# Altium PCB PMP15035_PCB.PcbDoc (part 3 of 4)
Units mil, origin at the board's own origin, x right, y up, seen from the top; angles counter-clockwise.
Board outline 5645 x 4585 mil, 8 copper layers (Top Layer, Signal Layer 1, Signal Layer 2, Signal Layer 3, Signal Layer 4, Signal Layer 5, Signal Layer 6, Bottom Layer), stack 60.9 mil thick; 335 components, 164 nets, 981 pads, 1349 vias.
Unrouted connection lines stored in the file: 46.
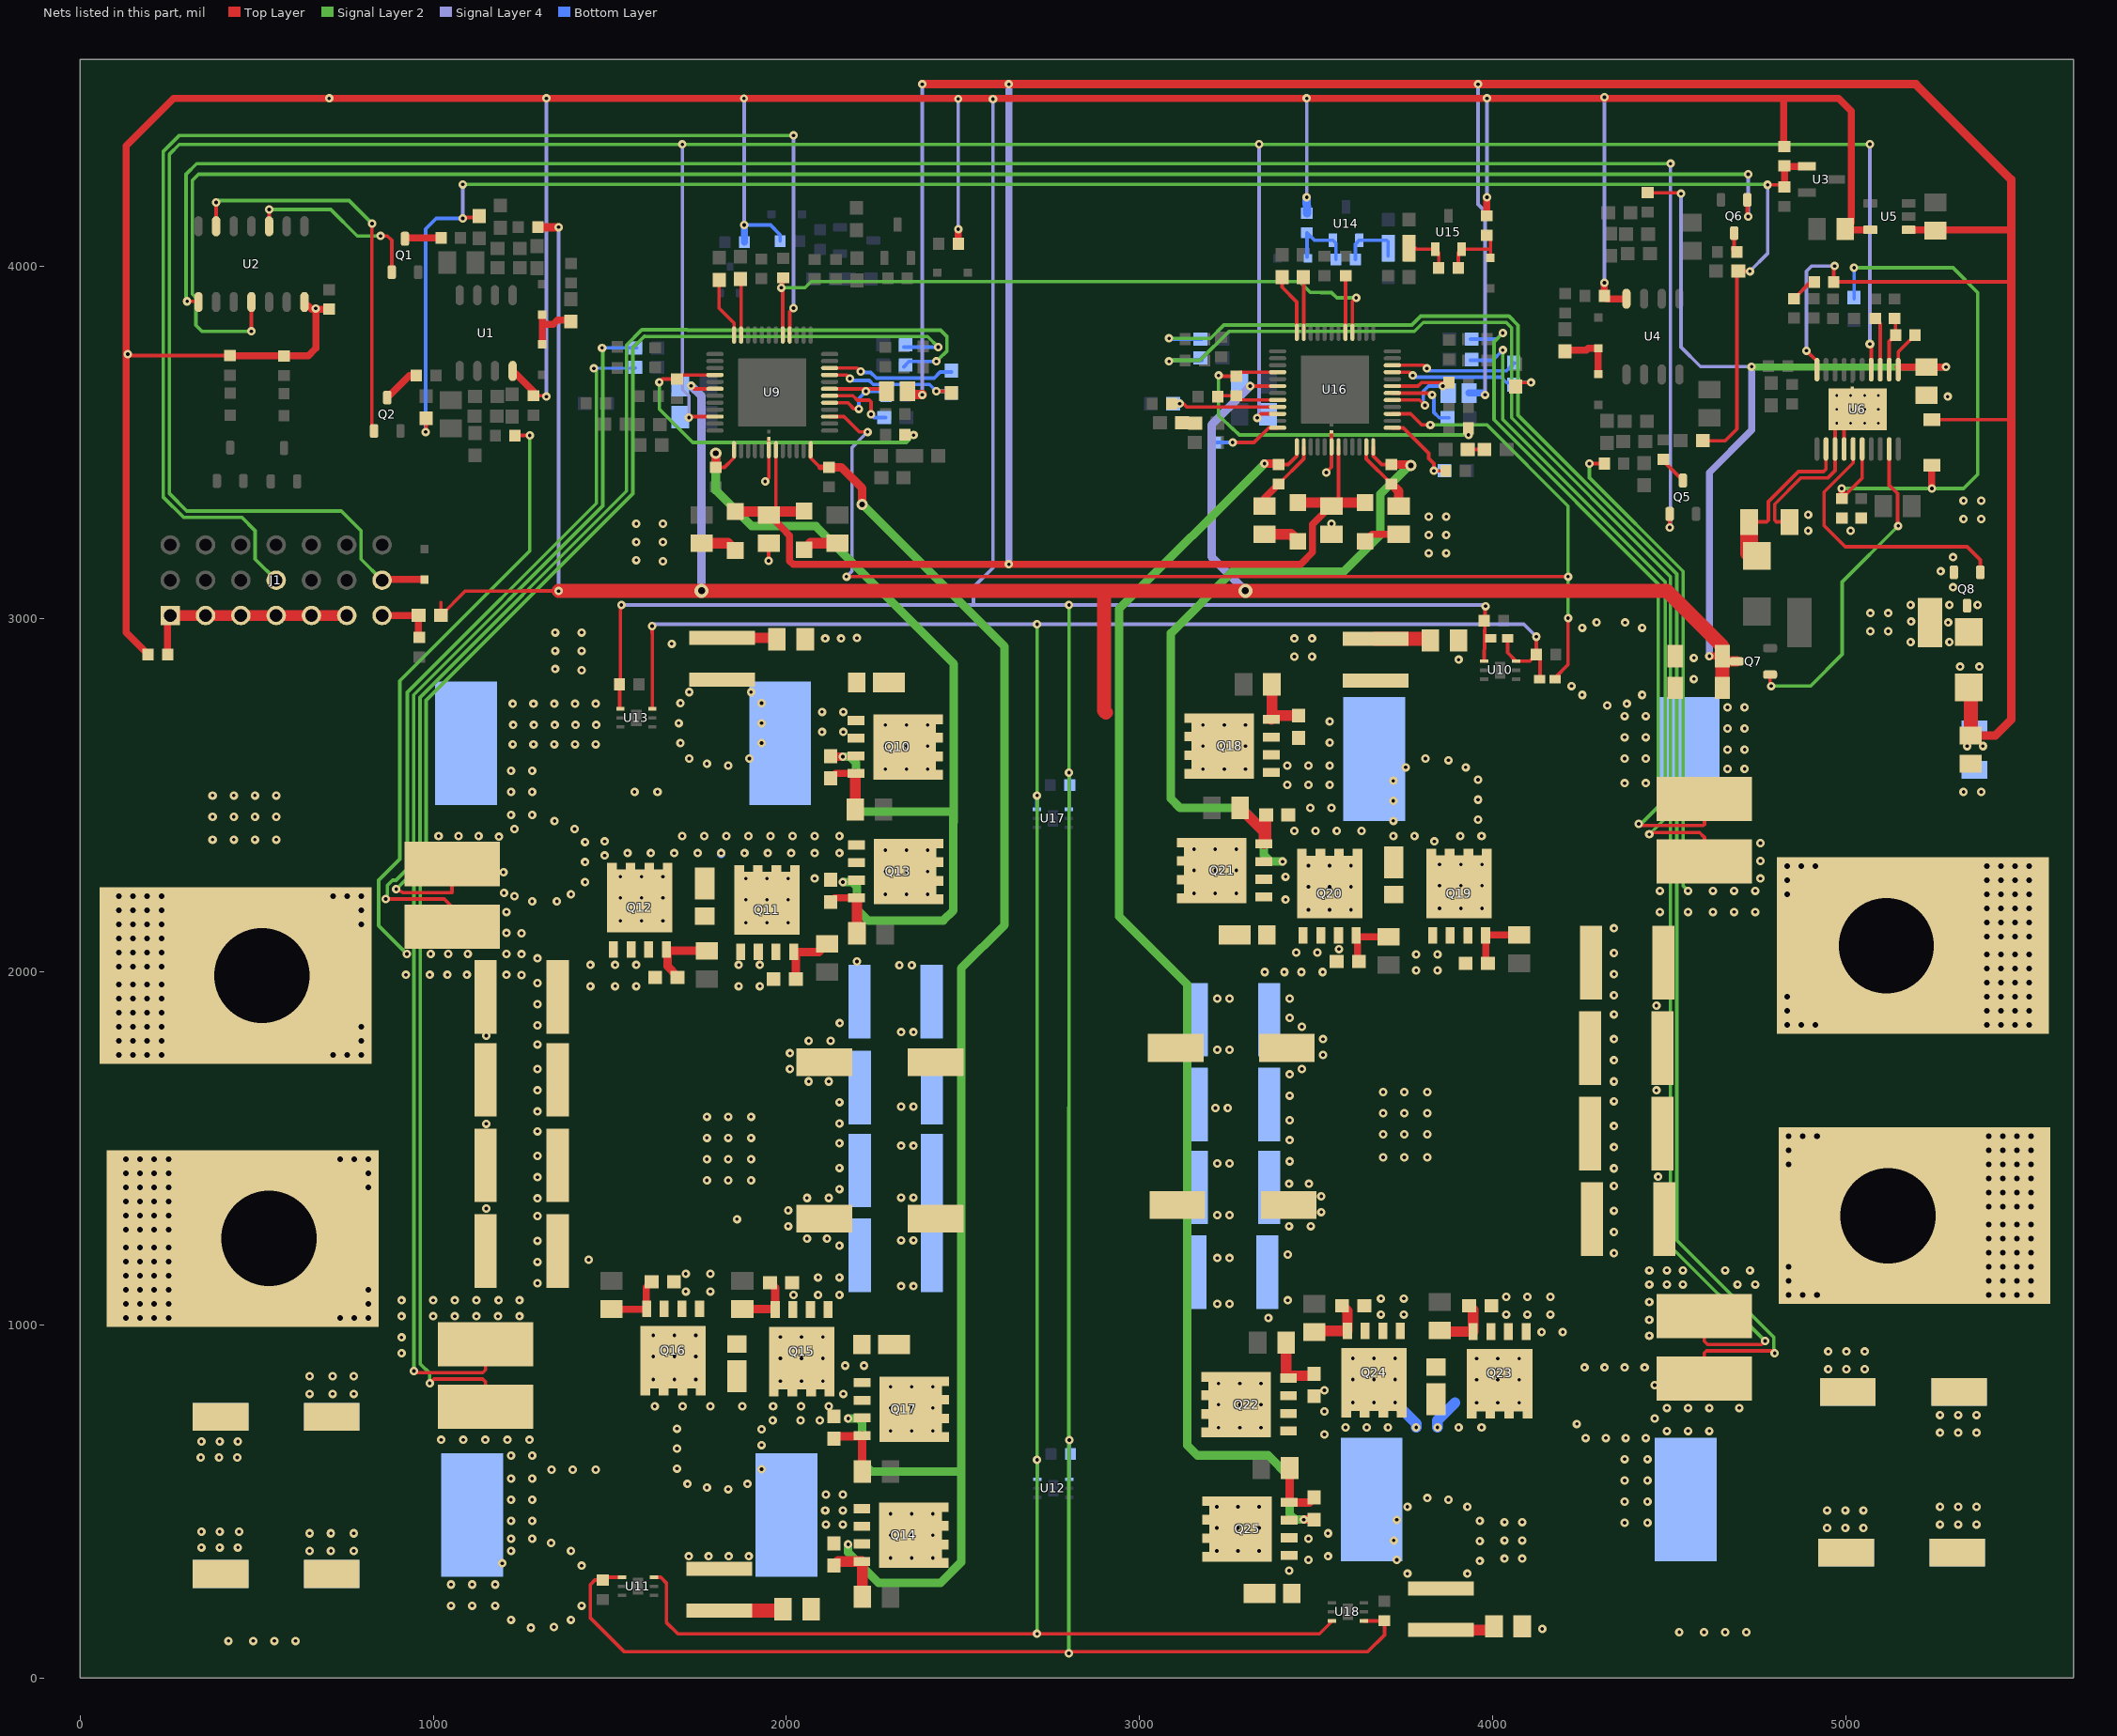
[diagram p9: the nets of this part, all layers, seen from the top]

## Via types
v1: diameter 24, hole 10, Top Layer to Bottom Layer, tented both sides, 873 vias
v2: diameter 32, hole 16, Top Layer to Bottom Layer, 237 vias
v3: diameter 24, hole 10, Top Layer to Bottom Layer, 145 vias
v4: diameter 19.68, hole 7.87, Top Layer to Bottom Layer, 62 vias
v5: diameter 32, hole 16, Top Layer to Bottom Layer, tented both sides, 14 vias
v6: diameter 23, hole 10, Top Layer to Bottom Layer, tented both sides, 5 vias
v7: diameter 19.68, hole 7.87, Top Layer to Bottom Layer, tented top, 4 vias
v8: diameter 19.68, hole 7.87, Top Layer to Bottom Layer, tented bottom, 2 vias
v9: diameter 40, hole 20, Top Layer to Bottom Layer, tented both sides, 2 vias
v10: diameter 24, hole 10, Top Layer to Bottom Layer, tented bottom, 2 vias
v11: diameter 22, hole 10, Top Layer to Bottom Layer, tented both sides, 1 vias
v12: diameter 24/24/24/24/24/24/24/24 (per signal layer), hole 10, Top Layer to Bottom Layer, tented both sides, 1 vias
v13: diameter 26, hole 10, Top Layer to Bottom Layer, tented both sides, 1 vias

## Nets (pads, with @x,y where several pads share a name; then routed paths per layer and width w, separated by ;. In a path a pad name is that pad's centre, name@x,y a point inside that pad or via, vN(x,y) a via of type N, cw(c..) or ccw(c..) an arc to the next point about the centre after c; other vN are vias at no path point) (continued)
NetC62_1: C62.1 R67.1 R72.2 U14.1 | length 183.2
  Bottom Layer w10: C62.1@3611.31,4018.7 3611.31,4061.66 U14.1@3622.4,4072.76 3699.99,4072.76 R72.2@3704.25,4068.5 R67.1@3704.25,4031.5 R67.1@3704.25,4027.56
NetC62_2: C62.2 D16.1 R66.2 U14.2 | length 209.1
  Bottom Layer w10: D16.1@3474.24,4025.26 R66.2@3474.24,4094.39 3495.88,4072.76 U14.2@3547.6,4072.76 3556.19,4064.17 C62.2@3556.19,4018.7
NetC63_1: C63.1 R69.1 R73.2 U15.1 | length 184.2
  Top Layer w10: R69.1@3763.75,4027.56 R69.1@3763.75,4031.5 R73.2@3763.75,4068.5 ; R73.2@3763.75,4072.44 R73.2@3763.75,4068.5 ; C63.1@3847.44,3995 3847.44,4037.91 U15.1@3837.6,4047.76 3784.5,4047.76 R73.2@3763.75,4068.5
NetC63_2: C63.2 D17.1 R68.2 U15.2 | length 192.7
  Top Layer w10: C63.2@3902.56,3995 3902.56,4037.91 U15.2@3912.4,4047.76 3991.5,4047.76 3993.75,4050 ; D17.1@3993.75,4023.31 3993.75,4050 ; R68.2@3993.75,4076.87 3993.75,4050
NetC65_1: C65.1 R70.1 | length 54.9
  Top Layer w10: C65.1@3925.76,3480 R70.1@3980.64,3480
NetC66_1: C66.1 R71.2 U16.8 | length 176
  Top Layer w10: C66.1@3221.31,3630 3223.75,3632.44 R71.2@3273.75,3632.44 3285.72,3620.47 U16.8@3391.35,3620.47
NetC73_2: C73.2 R77.1 U16.23 | length 205.5
  Top Layer w10: U16.23@3642.33,3487.6 3642.33,3453.86 C73.2@3713.75,3382.44
  Top Layer w26: C73.2@3713.75,3382.44 3733.75,3362.44 R77.1@3733.75,3320
NetC78_1: C78.1 R83.1 U16.14 | length 213.7
  Top Layer w10: C78.1@3393.75,3382.44 3465.17,3453.86 U16.14@3465.17,3487.6
  Top Layer w20: R83.1@3353.75,3320 3353.75,3342.44 C78.1@3393.75,3382.44
NetC80_1: C80.1 U16.12 | length 193.1
  Top Layer w10: v1(3263.75,3500) 3324.2,3500 3365.94,3541.73 U16.12@3391.35,3541.73
  Bottom Layer w10: C80.1@3215.56,3500 v1(3263.75,3500)
NetC85_2: C85.2 R86.2 | length 43.6
  Top Layer w10: R86.2@3118.16,3554.41 C85.2@3161.74,3554.41
NetC86_1: C86.1 R84.2 U16.9 | length 282
  Top Layer w10: v1(3113.75,3610) 3124.54,3610 3134.14,3600.39 3391.35,3600.39 U16.9@3391.35,3600.79
NetC87_1: C87.1 R85.2 U16.25 | length 251.9
  Top Layer w10: U16.25@3716.15,3541.73 3747.02,3541.73 3818.87,3469.87 3818.87,3455.13 3833.75,3440.25 v1(3833.75,3420) ; v1@3837.88,3420 C87.1@3867.49,3420
  Bottom Layer w10: v1(3833.75,3420) R85.2@3867.49,3420
NetC92_1: C92.1 R89.1 | length 151
  Top Layer w30: R89.1@1818.15,2946.48 C92.1@1969.15,2946.48
NetC93_1: C93.1 R101.1 | length 131.7
  Top Layer w40: R101.1@1835,191 C93.1@1966.67,191
NetC110_1: C110.1 R113.1 | length 151
  Top Layer w40: R113.1@3668.47,2943.41 C110.1@3819.47,2943.41
NetC111_1: C111.1 R125.1 | length 139.3
  Top Layer w30: R125.1@3853.75,136 C111.1@3993.06,136
NetD1_1: D1.1 D2.1 R7.1 | length 170.3
  Top Layer w20: D2.1@1308.39,3778.31 1308.39,3834.19 ; D1.1@1308.39,3861.69 1308.39,3834.19 ; R7.1@1390,3846.87 1351.76,3846.87 1339.07,3834.19 1308.39,3834.19
NetD5_1: D5.1 D6.1 R22.1 | length 169.2
  Top Layer w20: R22.1@4205.36,3761.89 4265.45,3761.89 4270.57,3767.01 D6.1@4299.06,3767.01 D5.1@4299.06,3693.62
NetD8_2: D8.2 L1.2 Q8.3
  other v1: 5183.75,2935 5293.75,2935 5290.25,2990 5184.93,2992.63 5293.75,3039.49 5373.75,3039.49 5183.75,3040
NetD9_2: D9.2 R34.2 U6.12 | length 455.9
  Top Layer w10: R34.2@4726.66,3275 4776.01,3275 4781.01,3280 4781.01,3332.54 4866.34,3417.87 4937.62,3417.87 4944.18,3424.43 U6.12@4944.18,3481.8
  Top Layer w50: D9.2@4726.66,3186.65 R34.2@4726.66,3275
NetD12_1: D12.1 R53.2 | length 102.6
  Top Layer w30: D12.1@2050.16,3195.83 2068.94,3214.61 R53.2@2145,3214.61
NetD13_1: D13.1 R58.2 | length 103.3
  Top Layer w30: R58.2@1760,3214.61 1834.88,3214.61 D13.1@1855,3194.49
NetD18_1: D18.1 R77.2 | length 103.3
  Top Layer w20: D18.1@3638.75,3219.88 3658.87,3240 R77.2@3733.75,3240
NetD19_1: D19.1 R83.2 | length 103.3
  Top Layer w30: R83.2@3353.75,3240 3428.63,3240 D19.1@3448.75,3219.88
NetJ1_1: J1.1 J1.4 J1.7 J1.10 J1.13 J1.16 R59.1 | length 613.1
  Top Layer w20: R59.1@247.56,2900 247.56,3002.56 J1.1@255,3010
  Top Layer w30: J1.1@255,3010 J1.4@355,3010 J1.7@455,3010 J1.10@555,3010 J1.13@655,3010 J1.16@755,3010
NetJ1_19: J1.19 R63.2 R64.2 | length 161.6
  Top Layer w20: J1.19@855,3010 947.44,3010 957.44,3000 R64.2@957.44,2945
NetL8_1: L8.1 R87.2 R103.2 | length 2119.5
  Top Layer w10: v1(895,2235) 915,2225 1052.76,2225 1053.15,2225.39 R87.2@1053.15,2306.06
  Signal Layer 2 w10: v1(895,2235) 944.25,2284.25 944.25,2784.81 1479.87,3320.43 1479.87,3766.23 v1(1477.99,3768.11) v1@1475.16,3770.94
  Bottom Layer w10: v1(1477.99,3768.11) R103.2@1572.01,3768.11 R103.2@1575.95,3768.11
  other v1: 1280,2200 1350,2200 1229.96,2215 1390,2220 1200,2224.21 1430,2254.96 1198.82,2282.57 1430,2311.64 1485,2330 1430,2368.32 1485,2370 1186.18,2383.32 1014.96,2385 1071.64,2385 1128.32,2385 1230,2405 1400.04,2405 1343.36,2427.43 1220,2445 1280,2445 1220,2510 1280,2510 1220,2570 1280,2570 1225,2645 1283.75,2645 1342.5,2645 1401.25,2645 1460,2645 1226.25,2700 1285,2700 1343.75,2700 1402.5,2700 1461.25,2700 1225,2760 1283.75,2760 1342.5,2760 1401.25,2760 1460,2760
NetL9_2: L9.2 R93.2 R99.2 | length 4420.2
  Top Layer w10: v1(990,835) 1002.13,847.13 1140,847.13 1148.15,838.98 R99.2@1148.15,768.9
  Signal Layer 2 w10: v1(990,835) 990,862.87 962.87,890 962.87,2252.32 980,2269.44 980,2770 1565,3355 1565,3768.6 1598.2,3801.8 1600,3800 2400,3800 v1(2430,3770)
  Bottom Layer w10: R93.2@2332.56,3770 v1(2430,3770)
  other v1: 1276.64,142.57 1341.9,144.28 1219.96,165 1390,165 1050,205 1110,205 1175,205 1420,205 1050,265 1110,265 1175,265 1420,318.36 1195,325 1219.96,360 1390,360 1333.32,382.43 1220,395 1280,395 1220,445 1280,445 1220,505 1280,505 1220,565 1280,565 1335,590 1395,590 1460,590 1220,630 1280,630 1022.5,675 1085,675 1147.5,675 1210,675 1272.5,675
NetL10_2: L10.2 R111.1 R116.2 | length 1980.5
  Top Layer w10: v1(4413.75,2420) 4418.75,2415 4596.19,2415 4599.97,2418.78 R111.1@4599.97,2490.59
  Signal Layer 2 w10: v1(4028.75,3810) 4003.87,3785.13 4003.87,3564.87 4468.75,3100 4468.75,2467.87 4420.87,2420 v1(4413.75,2420)
  Bottom Layer w10: R116.2@3936.86,3792.8 R116.2@3940.8,3792.8 4011.54,3792.8 v1(4028.75,3810)
  other v1: 4373.75,2535 4433.75,2535 4665,2575.59 4713.75,2575.59 4373.75,2605 4433.75,2605 4665,2630 4713.75,2630 4373.75,2665 4433.75,2665 4665,2690 4713.75,2690 4373.75,2725 4433.75,2725 4665,2750 4713.75,2750 4325,2755 4380,2760 4253.71,2785 4423.75,2785 4223.75,2810 4253.71,2975 4423.75,2975 4375,2990 4294.53,2990.86
NetL11_1: L11.1 R123.1 R126.2 | length 4605.9
  Top Layer w10: R123.1@4599.59,847.94 4599.59,920.85 4605.87,927.13 4791.62,927.13 v1(4798.75,920)
  Signal Layer 2 w10: v1(3083.75,3795) 3200.99,3795 3238.74,3832.75 3771.22,3832.75 3796.28,3857.81 4046.21,3857.81 4071.62,3832.4 4071.62,3577.4 4521.62,3127.4 4521.62,1240.18 4796.5,965.3 4796.5,922.25 v1(4798.75,920)
  Bottom Layer w10: v1@3085.95,3792.8 R126.2@3172.29,3792.8 R126.2@3176.23,3792.8
  other v1: 4373.75,440 4438.75,440 4373.75,500 4438.75,500 4373.75,560 4438.75,560 4373.75,620 4438.75,620 4263.71,680 4320.39,680 4377.07,680 4433.75,680 4493.75,700 4553.75,700 4613.75,700 4238.75,720 4458.75,735 4493.75,765 4553.75,765 4613.75,765 4698.75,765 4458.75,830 4260.39,880 4317.07,880 4373.75,880 4430.43,880
NetQ1_1: Q1.1 U2.3 | length 520.8
  Top Layer w10: U2.3@535,4112.6 v1(535,4160) ; v1(850.79,4085) 870,4085 882.28,4072.72 Q1.1@882.28,3982.76
  Signal Layer 2 w10: v1(535,4160) 710,4160 785,4085 v1(850.79,4085)
NetQ1_3: Q1.3 R12.1 | length 99.7
  Top Layer w20: Q1.3@922.44,4080 R12.1@1022.13,4080
NetQ2_1: Q2.1 U2.6 | length 1128.6
  Top Layer w10: U2.6@385,4112.6 v1(385,4180) ; v1(826.83,4120) 825.91,4119.09 825.91,3539.13 Q2.1@832.28,3532.76
  Signal Layer 2 w10: v1(385,4180) 390.13,4185.13 761.7,4185.13 v1(826.83,4120)
NetQ2_3: Q2.3 R11.1 | length 108.4
  Top Layer w20: Q2.3@869.68,3627.24 932.44,3690 R11.1@952.13,3690
NetQ5_1: Q5.1 U2.8 | length 5681
  Top Layer w10: v1(302.91,3900) 333.03,3900 U2.8@335,3898.03 ; v1(4501.35,3259.11) Q5.1@4501.35,3297.76
  Signal Layer 2 w10: v1(302.91,3900) 300,3902.91 300,4260 330,4290 v1(4503.75,4290)
  Signal Layer 4 w10: v1(4501.35,3259.11) 4503.94,3261.7 4503.94,3603.21 4503.75,3603.4 v1(4503.75,4290)
NetQ5_3: Q5.3 R28.1 | length 82.8
  Top Layer w10: R28.1@4484.06,3452.44 4484.06,3446.93 Q5.3@4538.75,3392.24
NetQ6_1: Q6.1 U2.11 | length 5239.8
  Top Layer w10: v1(485,3815) U2.11@485,3898.03 ; v1@4721.46,4142.91 Q6.1@4721.46,4187.56
  Signal Layer 2 w10: v1(485,3815) 345,3815 327.79,3832.21 327.79,3910.3 317.87,3920.22 317.87,4242.87 335,4260 v1(4724.06,4260)
  Signal Layer 4 w10: v1(4724.06,4140.31) v1(4724.06,4260)
NetQ6_3: Q6.3 R27.1 | length 55.9
  Top Layer w10: R27.1@4684.06,4047.87 Q6.3@4684.06,4093.07
  Top Layer w20: R27.1@4684.38,4047.56 R27.1@4691.94,4040
NetQ7_1: Q7.1 U6.19 | length 922.3
  Top Layer w10: v1@4785.99,2812.76 Q7.1@4785.99,2842.6 ; U6.19@5123.31,3481.8 5123.31,3378.97 5146.62,3355.67 v1@5146.62,3267.13
  Signal Layer 2 w10: v1(4788.75,2810) 4900,2810 4990,2900 4990,3105.09 v1(5148.75,3263.83)
NetQ8_1: Q8.1 U6.15 | length 768.9
  Top Layer w10: U6.15@5020.95,3481.8 5020.95,3442.2 4938.75,3360 4938.75,3265 4998.75,3205 5343.75,3205 5381.15,3167.6 Q8.1@5381.15,3132.24
NetQ10_4: Q10.4 R88.1 R94.2 | length 178.3
  Top Layer w20: R88.1@2125,2548.5 2138.98,2562.48 Q10.4@2196.93,2562.48
  Top Layer w30: R94.2@2195,2460 Q10.4@2195,2560.55
NetQ11_4: Q11.4 R90.2 R95.2 | length 175.1
  Top Layer w24: Q11.4@2020.47,2057.16 2092.16,2057.16 R95.2@2115,2080 ; R90.2@2026.5,1980 Q11.4@2026.5,2051.14
NetQ12_4: Q12.4 R91.2 R96.2 | length 197.7
  Top Layer w24: R91.2@1691.5,1985 1691.5,1988.5 1663.78,2016.22 1663.78,2060 R96.2@1775,2060
NetQ13_4: Q13.4 R97.1 R98.2 | length 177.3
  Top Layer w20: R97.1@2125,2198.5 2136.5,2210 Q13.4@2198.78,2210
  Top Layer w30: R98.2@2200,2110 Q13.4@2200,2208.78
NetQ14_4: Q14.4 R100.1 R106.2 | length 166.1
  Top Layer w30: R100.1@2146.5,330 Q14.4@2213.78,330 ; R106.2@2215,230 Q14.4@2215,328.78
NetQ15_4: Q15.4 R104.1 R107.2 | length 174.2
  Top Layer w24: R107.2@1875,1045 Q15.4@1966.85,1045 ; R104.1@1953.5,1120 1968.15,1105.35 Q15.4@1968.15,1043.7
NetQ16_4: Q16.4 R105.1 R108.2 | length 182.2
  Top Layer w20: R108.2@1505,1045 1602.83,1045 1602.83,1107.17 R105.1@1618.5,1122.83
NetQ17_4: Q17.4 R109.1 R110.2 | length 173.1
  Top Layer w24: R109.1@2140,685 Q17.4@2210.91,685 ; Q17.4@2214.29,686.89 2215,686.18 R110.2@2215,585
NetQ18_4: Q18.4 R112.1 R118.2 | length 179
  Top Layer w30: Q18.4@3373.12,2715.51 Q18.4@3375,2717.39 ; R118.2@3375,2815 Q18.4@3375,2717.39 ; R112.1@3450,2726.5 3384.1,2726.5 Q18.4@3375,2717.39
NetQ19_4: Q19.4 R114.2 R119.2 | length 168.5
  Top Layer w20: R114.2@3981.22,2030.28 3981.22,2105 R119.2@4075,2105
NetQ20_4: Q20.4 R115.2 R120.2 | length 153.5
  Top Layer w20: R115.2@3617.05,2034.44 3617.05,2100 R120.2@3705,2100
NetQ21_4: Q21.4 R121.1 R122.2 | length 214.6
  Top Layer w30: R122.2@3285,2465 3352.29,2397.71 Q21.4@3352.29,2362.91 3358.5,2369.13 R121.1@3358.5,2445
NetQ22_4: Q22.4 R124.1 R130.2 | length 168.5
  Top Layer w30: R130.2@3415,950 3415,856.35 R124.1@3489.85,856.35
NetQ23_4: Q23.4 R128.1 R131.2 | length 153.5
  Top Layer w30: R131.2@3853.78,981.22 Q23.4@3945,981.22 R128.1@3945,1043.5
NetQ24_4: Q24.4 R129.1 R132.2 | length 168.5
  Top Layer w30: R132.2@3498.46,983.46 Q24.4@3588.98,983.46 3588.98,1039.52 R129.1@3573.5,1055
NetQ25_4: Q25.4 R133.1 R134.2 | length 175.2
  Top Layer w24: R134.2@3425,595 3425,498.81 Q25.4@3423.67,497.48 3480.98,497.48 R133.1@3495,511.5
NetR30_1: R30.1 R31.2 U6.2 | length 150.2
  Top Layer w10: U6.2@5123.31,3706.2 5123.31,3786.13 R30.1@5141.19,3804 R31.2@5141.19,3849
NetR33_2: R33.2 U6.3 | length 151
  Top Layer w10: R33.2@5083.75,3851.44 5097.72,3837.46 U6.3@5097.72,3706.2
NetR37_2: R37.2 R38.1 | length 77.1
  Top Layer w10: R37.2@4853.75,3907.56 4901.19,3955 R38.1@4911.19,3955
NetR48_1: R48.1 R49.1 U9.33 | length 406.2
  Top Layer w10: U9.33@2122.56,3691.42 2169.69,3691.42 v1(2180.16,3680.94) ; v1(2425,3645) 2467.01,3645 R48.1@2467.36,3644.65
  Bottom Layer w10: v1(2180.16,3680.94) 2185.03,3676.07 2234.23,3676.07 2245.58,3664.72 2405.28,3664.72 v1(2425,3645) R49.1@2467.01,3645
NetR49_2: R49.2 U9.34 | length 363.7
  Top Layer w10: U9.34@2122.56,3711.1 2122.72,3710.94 2200.16,3710.94 v1(2210.16,3700.94)
  Bottom Layer w10: v1(2210.16,3700.94) 2212.4,3698.7 2238.69,3698.7 2254.79,3682.6 2418.5,3682.6 2435.67,3699.76 R49.2@2467.36,3699.76
NetR52_1: R52.1 U9.48 | length 177.6
  Top Layer w10: R52.1@1809.53,3964.65 1809.53,3880.47 1851.89,3838.11 U9.48@1851.89,3804.61
NetR55_2: R55.2 U9.47 | length 158
  Top Layer w10: U9.47@1871.57,3804.61 R55.2@1871.57,3962.6
NetR57_2: R57.2 U9.30 | length 205.4
  Top Layer w10: U9.30@2122.56,3632.36 2188.74,3632.36 2201.1,3620 2235,3620 2240,3615 v1(2240,3580) v1@2240.94,3580.94
  Bottom Layer w10: v1(2240,3580) 2249.06,3570.94 R57.2@2280.67,3570.94
NetR74_1: R74.1 R75.1 U16.33 | length 452.4
  Top Layer w10: U16.33@3716.15,3699.21 3764.54,3699.21 v1(3773.75,3690) ; R74.1@4060.95,3669.64 v1@4108.39,3669.64
  Bottom Layer w10: v1(3773.75,3690) 3778.62,3685.13 4023.94,3685.13 4039.42,3669.64 4060.95,3669.64 4108.39,3669.64 v1(4108.75,3670)
NetR75_2: R75.2 U16.34 | length 360.2
  Top Layer w10: U16.34@3716.15,3718.9 3804.85,3718.9 v1(3813.75,3710)
  Bottom Layer w10: v1(3813.75,3710) 3820.56,3703.19 4039.38,3703.19 R75.2@4060.95,3724.76
NetR76_1: R76.1 U16.48 | length 177.3
  Top Layer w10: R76.1@3403.75,3972.44 3403.75,3940 3445.48,3898.27 U16.48@3445.48,3812.4
NetR79_2: R79.2 U16.41 | length 159.6
  Top Layer w10: U16.41@3583.28,3812.4 R79.2@3583.28,3971.97
NetR80_2: R80.2 U16.47 | length 158.6
  Top Layer w10: U16.47@3465.17,3812.4 R80.2@3465.17,3971.02
NetR82_2: R82.2 U16.30 | length 208.2
  Top Layer w10: U16.30@3716.15,3640.16 v1@3823.59,3640.16
  Bottom Layer w10: v1(3828.75,3635) 3833.62,3630.13 3833.62,3585.13 3848.75,3570 R82.2@3876.19,3570
nFAULT: D14.2 U9.27 U16.27 | length 3711.9
  Top Layer w10: U9.27@2122.56,3573.31 2163.07,3573.31 2206.38,3530 v1(2230,3530) ; v1(2170,3120) v1(4213.75,3120) ; U16.27@3716.15,3581.1 3767.92,3581.1 3799.03,3550 v1(3823.75,3550) ; D14.2@4178,2834.92 4213.75,2870.67 v1(4213.75,3002.74) v1@4213.75,3005
  Signal Layer 2 w10: v1(3823.75,3550) 3983.75,3550 4213.75,3320 v1(4213.75,3120) v1(4213.75,3002.74)
  Signal Layer 4 w10: v1(2170,3120) 2186.13,3136.13 2186.13,3486.13 v1(2230,3530)
OTP: C60.1 D14.1 R50.1 U10.3 U11.3 U12.3 U13.3 U17.3 U18.3 | length 8036.8
  Top Layer w10: v1(1620,2980) 1620.05,2935.07 ; 1620.05,2945.07 1620.07,2930 U13.3@1620.28,2745.59 ; U11.3@1625.28,285.59 1644.41,285.59 1660,270 1660,158.22 1692.74,125.48 3509.98,125.48 3544.5,160 U18.3@3544.5,161.97 ; R50.1@4042.37,2945 4042.37,2904.76 U10.3@4066.62,2880.51 4104.38,2880.51 C60.1@4123.79,2899.92 ; v1@4123.79,2949.96 C60.1@4123.79,2899.92 ; D14.1@4134.69,2834.92 4134.69,2889.01 C60.1@4123.79,2899.92
  Signal Layer 2 w10: v1(2710,125.48) v1(2710,617.95) v1(2710,2500) v1(2710,2985)
  Signal Layer 4 w10: v1@1625,2985 v1(2710,2985) 4088.75,2985 v1(4123.75,2950)
  Bottom Layer w10: U17.3@2709.72,2460.87 v1@2709.72,2499.72 ; U12.3@2710,563.72 v1(2710,617.95)
PGND: C18.2 C19.2 C20.2 C22.2 C23.2 C27.2 C28.2 C45.2 C75.2 C92.2 C93.2 C94.2 C95.2 C96.2 C97.2 C98.2 C99.2 C100.2 C101.2 C102.2 C103.2 C104.2 C105.2 C106.2 C107.2 C108.2 C109.2 C110.2 C111.2 C112.2 C114.2 C115.2 C116.2 C117.2 C118.2 C119.2 C121.2 C122.2 C123.2 C126.2 C127.2 D21.2 D23.2 D25.2 D27.2 NT1.2 NT2.2 NT3.2 PGND.1 Q8.2 Q11.1 Q11.2 Q11.3 Q12.1 Q12.2 Q12.3 Q15.1 Q15.2 Q15.3 Q16.1 Q16.2 Q16.3 Q19.1 Q19.2 Q19.3 Q20.1 Q20.2 Q20.3 Q23.1 Q23.2 Q23.3 Q24.1 Q24.2 Q24.3 R34.1 R90.1 R91.1 R104.2 R105.2 R114.1 R115.1 R128.2 R129.2 U6.13 U6.14 U6.21 U9.18 U16.18 | length 860.6
  Top Layer w10: v1(1940,3389.61) 1950.31,3399.92 U9.18@1950.31,3479.8 ; v1(1950,3165) C45.2@1950,3214.61 ; U9.18@1950.16,3479.96 NT2.2@1950.16,3510.94 ; v1(3528.75,3415) 3543.91,3430.16 U16.18@3543.91,3487.6 3543.75,3487.76 NT3.2@3543.75,3530 ; R34.1@4840.83,3275 4803.75,3275 4798.89,3279.86 4798.89,3325.14 4873.75,3400 4949.77,3400 4969.77,3420 U6.13@4969.77,3481.8 4969.77,3549.71 v4(4974.69,3554.63) ; U6.14@4995.36,3481.8 4995.36,3555.61 U6.21@5033.75,3594
  other v1: 420,105 490,105 550,105 610,105 4528.75,130 4598.75,130 4658.75,130 4718.75,130 4140.6,139.21 4033.75,338.33 4083.75,338.33 343.33,370 395,370 446.67,370 4033.75,390 4083.75,390 343.33,415 395,415 450,415 5267.08,435 5318.75,435 5370.41,435 4033.75,441.67 4083.75,441.67 5267.08,485 5318.75,485 5370.41,485 341.67,625 393.33,625 445,625 343.33,670 395,670 446.67,670 5267.08,695 5318.75,695 5370.41,695 5267.08,745 5318.75,745 5370.41,745 4138.75,980 4198.75,980 3365,1020 3683.75,1030 3748.75,1030 4038.75,1030 4098.75,1030 4163.75,1030 3420,1070 3683.75,1075 3748.75,1075 4038.75,1080 4098.75,1080 4163.75,1080 2020,1085 2090,1085 2150,1085 1715,1095 1785,1095 1295,1118.81 1715,1145 1785,1145 1295,1178.81 1440,1185 3420,1200 4343.75,1203.81 2150,1225 1295,1238.81 2058.31,1245 2115,1245 4343.75,1263.81 2005,1280 3423.31,1280 3485,1280 1295,1308.81 3515,1320 4343.75,1323.81 2005,1325 1295,1358.81 2058.31,1360 2120,1360 3515,1365 2150,1385 4343.75,1393.81 3423.31,1400 3480,1400 1775,1410 1835,1410 1900,1410 1295,1418.81 4343.75,1443.81 2150,1445 3425,1463.81 1775,1470 1835,1470 1900,1470 3690,1475 3750,1475 3815,1475 1295,1478.81 4343.75,1503.81 2150,1515 3425,1523.81 1775,1530 1835,1530 1900,1530 3690,1540 3750,1540 3815,1540 1295,1548.81 4343.75,1563.81 2150,1571.19 3425,1580 1775,1590 1835,1590 1900,1590 3690,1600 3750,1600 3815,1600 1295,1605 2150,1631.19 4343.75,1633.81 3425,1650 3690,1660 3750,1660 3815,1660 1295,1665 2063.31,1690 2120,1690 4343.75,1690 3425,1710 1295,1725 2010,1725 3460,1725 4343.75,1750 3520,1765 2010,1770 1295,1795 2063.31,1805 2125,1805 3520,1810 4343.75,1810 3460,1845 1295,1848.81 2151.2,1855 3425,1870 4343.75,1880 1295,1908.81 3425,1925 4343.75,1933.81 1445,1960 1515,1960 1575,1960 1865,1960 1925,1960 1295,1968.81 4343.75,1993.81 3355,2000 3410,2000 3458.75,2000 3518.75,2000 3783.75,2005 3843.75,2005 1445,2020 1515,2020 1575,2020 1865,2020 1925,2020 2200,2030 1295,2038.81 3783.75,2050 3843.75,2050 4343.75,2053.81 3443.75,2055 3503.75,2055 3565,2065 4343.75,2123.81 375,2375 435,2375 495,2375 555,2375 375,2440 435,2440 495,2440 555,2440 375,2500 435,2500 495,2500 555,2500 1570,2510 1635,2510 5333.75,2510 5383.75,2510 4570,2830 1420,2855 1345,2858.33 3903.75,2885 4570,2890 3438.75,2893.33 3488.75,2893.33 1345,2910 1420,2910 1675,2930 2110,2945 2155,2945 3438.75,2945 3488.75,2945 2200,2946.06 1345,2961.67 1420,2961.67 5070,2965 5120,2965 5070,3016.67 5120,3016.67 5303.75,3090 5268.75,3135 1650,3163.33 1575,3166.67 5303.75,3175 3818.75,3186.67 3868.75,3186.67 1575,3218.33 1650,3218.33 3818.75,3238.33 3868.75,3238.33 4893.75,3250 5013.75,3250 1575,3270 1650,3270 3543.75,3270 5333.75,3283.33 5383.75,3283.33 3818.75,3290 3868.75,3290 4893.75,3295 5333.75,3335 5383.75,3335 5288.75,3630
  other v2: 110,1765 150,1765 190,1765 230,1765 716.27,1765 756.27,1765 796.27,1765 110,1805 150,1805 190,1805 230,1805 796.27,1805 110,1845 150,1845 190,1845 230,1845 796.27,1845 4833.77,1850 4873.77,1850 4913.77,1850 5400.04,1850 5440.04,1850 5480.04,1850 5520.04,1850 110,1885 150,1885 190,1885 230,1885 4833.77,1890 5400.04,1890 5440.04,1890 5480.04,1890 5520.04,1890 110,1925 150,1925 190,1925 230,1925 4833.77,1930 5400.04,1930 5440.04,1930 5480.04,1930 5520.04,1930 110,1965 150,1965 190,1965 230,1965 5400.04,1970 5440.04,1970 5480.04,1970 5520.04,1970 5400.04,2010 5440.04,2010 5480.04,2010 5520.04,2010 110,2015 150,2015 190,2015 230,2015 5400.04,2050 5440.04,2050 5480.04,2050 5520.04,2050 110,2055 150,2055 190,2055 230,2055 110,2095 150,2095 190,2095 230,2095 5400.04,2100 5440.04,2100 5480.04,2100 5520.04,2100 110,2135 150,2135 190,2135 230,2135 796.27,2135 5400.04,2140 5440.04,2140 5480.04,2140 5520.04,2140 110,2175 150,2175 190,2175 230,2175 796.27,2175 5400.04,2180 5440.04,2180 5480.04,2180 5520.04,2180 110,2215 150,2215 190,2215 230,2215 716.27,2215 756.27,2215 796.27,2215 4833.77,2220 5400.04,2220 5440.04,2220 5480.04,2220 5520.04,2220 4833.77,2260 5400.04,2260 5440.04,2260 5480.04,2260 5520.04,2260 4833.77,2300 4873.77,2300 4913.77,2300 5400.04,2300 5440.04,2300 5480.04,2300 5520.04,2300
  other v3: 1860,1300
  other v4: 5014.06,3554.63 5053.43,3554.63 5092.8,3554.63 4974.69,3594 5014.06,3594 5053.43,3594 5092.8,3594 4974.69,3633.37 5014.06,3633.37 5053.43,3633.37 5092.8,3633.37
  other v10: 2090,1135 2150,1135
REF: C8.1 R8.2 R9.1 R14.2 R23.2 R24.1 U3.1 | length 5600.1
  Top Layer w10: v1@979.68,3531.3 R9.1@979.68,3572.44 ; v1(1083.39,4135) 1085.94,4137.56 R8.2@1129.68,4137.56 ; R23.2@4591.31,3505 4658.75,3505 4691.62,3537.87 4691.62,3985.31 v1@4728.43,3985.31 ; v1(4778.75,4230) C8.1@4826.31,4230
  Top Layer w20: C8.1@4826.31,4223.86 4826.31,4255 4826.31,4273.66 R14.2@4831.35,4278.7 ; R14.2@4826.31,4283.74 4827.65,4282.4 U3.1@4889.97,4282.4
  Signal Layer 2 w10: v1(1083.39,4231.25) v1@4773.75,4231.25
  Signal Layer 4 w10: v1(1083.39,4135) v1(1083.39,4231.25) ; v1(4728.75,3985) 4778.75,4035 v1(4778.75,4230)
  Bottom Layer w10: v1(978.39,3530) 978.39,4105 1008.39,4135 v1(1083.39,4135)
SW11: C48.2 D21.1 D22.2 L8.2 Q10.1 Q10.2 Q10.3 Q11.5 Q11.6 Q11.7 Q11.8 Q11.9 Q12.5 Q12.6 Q12.7 Q12.8 Q12.9 Q13.1 Q13.2 Q13.3 R88.2 R89.2 R97.2 U9.13 | length 2730
  Top Layer w10: C48.2@1800.16,3429.76 1824.76,3429.76 1851.89,3456.89 U9.13@1851.89,3479.8
  Top Layer w24: v5(1800,3470) C48.2@1800.16,3429.76 ; R88.2@2126.5,2610 v1(2160,2610)
  Signal Layer 2 w24: v5(1800,3470) 1800,3365 1901.87,3263.13 2083.52,3263.13 2474.21,2872.43 2474.21,2865 2473.5,2610 2473.5,2425.38 ; v1(2160,2255) 2186.26,2255 2200,2241.26 2200,2177.44 2231.57,2145.87 2444.13,2145.87 2473.13,2174.87 2473.13,2455 2210,2455 2196.93,2468.07 2196.93,2593.07 2180,2610 v1(2160,2610)
  Bottom Layer w24: v1@1815,2335 v1(1815,2336.69)
  other v1: 2080,2265 1550,2336.69 1616.25,2336.69 1682.5,2336.69 1748.75,2336.69 1881.25,2336.69 1947.5,2336.69 2013.75,2336.69 2080,2336.69 2150,2336.69 1705,2385 1767.5,2385 1830,2385 1892.5,2385 1955,2385 2017.5,2385 2080,2385 2150,2385 1835,2585 1775,2590 1724.96,2605 1895,2605 1700,2648.32 1930,2648.32 2100.91,2680 2160.91,2680 1695,2705 1930,2705 2100.91,2736.99 2160.91,2736.99 1700,2761.68 1930,2761.68 1725,2792.99 1900,2792.99
  other v3: 1885,2140 1945,2140 2005,2140 1530,2145 1590,2145 1650,2145 1885,2205 1945,2205 2005,2205 1530,2210 1590,2210 1650,2210 1885,2265 1945,2265 2005,2265 1530,2270 1590,2270 1650,2270
SW12: C73.1 D25.1 D26.2 L10.1 Q18.1 Q18.2 Q18.3 Q19.5 Q19.6 Q19.7 Q19.8 Q19.9 Q20.5 Q20.6 Q20.7 Q20.8 Q20.9 Q21.1 Q21.2 Q21.3 R112.2 R113.2 R121.2 U16.24 | length 1974.5
  Top Layer w10: U16.24@3662.02,3487.6 3662.02,3461.73 3686.19,3437.56 C73.1@3713.75,3437.56
  Top Layer w24: C73.1@3713.75,3437.56 v5@3756.19,3437.56
  Signal Layer 2 w24: v1(3405,2312.91) 3370.91,2312.91 3352.29,2331.53 3352.29,2402.09 3289.38,2465 3115,2465 3088.75,2491.25 3088.75,2959.92 3262.58,3133.75 3577.65,3133.75 3681.87,3237.97 3681.87,3353.2 3763.67,3435 v5(3768.75,3435)
  other v1: 3413.75,2205 3413.75,2270 3835,2370 3718.75,2385 3778.75,2385 3908.75,2385 3968.75,2385 3438.75,2400 3498.75,2400 3558.75,2400 3628.75,2400 3718.75,2428.32 3958.75,2431.64 3483.75,2465 3543.75,2465 3718.75,2485 3958.75,2488.32 3418.75,2530 3478.75,2530 3538.75,2530 3718.75,2541.68 3958.75,2545 3753.71,2580 3923.75,2580 3418.75,2585 3478.75,2585 3538.75,2585 3875,2600 3810,2605 3538.75,2650 3538.75,2710
  other v3: 3478.55,2176.3 3538.55,2176.3 3598.55,2176.3 3850,2180 3910,2180 3970,2180 3478.55,2241.3 3538.55,2241.3 3598.55,2241.3 3850,2245 3910,2245 3970,2245 3478.55,2301.3 3538.55,2301.3 3598.55,2301.3 3850,2305 3910,2305 3970,2305
SW21: C43.1 D23.1 D24.2 L9.1 Q14.1 Q14.2 Q14.3 Q15.5 Q15.6 Q15.7 Q15.8 Q15.9 Q16.5 Q16.6 Q16.7 Q16.8 Q16.9 Q17.1 Q17.2 Q17.3 R100.2 R101.2 R109.2 U9.24 | length 4316.9
  Top Layer w10: U9.24@2068.43,3479.8 2068.43,3456.93 2095.59,3429.76
  Top Layer w16: 2095.59,3429.76 C43.1@2120.16,3429.76
  Top Layer w24: C43.1@2120.16,3429.76 2155.24,3429.76 2215,3370 v5(2215,3325)
  Signal Layer 2 w24: v1(2175,378.45) 2175,355.55 2260.55,270 2436.8,270 2495,328.2 2495,585 ; v1(2175,735) 2204.45,735 2215,724.45 2215,610 2240,585 2495,585 ; v5(2215,3325) 2618.13,2921.87 2618.13,2133.59 2495,2010.47 2495,585
  other v1: 1723.32,345 1780,345 1836.68,345 1893.36,345 2111.73,435 2160,435 2110,475 2160,475 2111.73,520 2160,520 1835,535 1775,540 1719.96,550 1890,550 1930,591.64 1690,593.32 1690,650 1930,660 1930,705 1690,706.68 1961.17,730 2040,730 2095,730 1627.33,769.98 1706.17,769.98 1785,769.98 1875,769.98 1962.33,769.98 2041.17,769.98 2120,769.98 2161.26,805 2166.26,885 2220,885
  other v3: 1983.15,840.91 2043.15,840.91 2103.15,840.91 1623.15,845.91 1683.15,845.91 1743.15,845.91 1983.15,905.91 2043.15,905.91 2103.15,905.91 1623.15,910.91 1683.15,910.91 1743.15,910.91 1983.15,965.91 2043.15,965.91 2103.15,965.91 1623.15,970.91 1683.15,970.91 1743.15,970.91
SW22: C78.2 D27.1 D28.2 L11.2 Q22.1 Q22.2 Q22.3 Q23.5 Q23.6 Q23.7 Q23.8 Q23.9 Q24.5 Q24.6 Q24.7 Q24.8 Q24.9 Q25.1 Q25.2 Q25.3 R124.2 R125.2 R133.2 U16.13 | length 3851
  Top Layer w10: C78.2@3393.75,3437.56 3421.31,3437.56 3445.48,3461.73 U16.13@3445.48,3487.6
  Top Layer w24: v1(3353.75,3440) C78.2@3391.31,3440 ; v1(3464.99,448.81) 3494.69,448.81 R133.2@3495,448.5
  Signal Layer 2 w24: v1(3353.75,3440) 2941.87,3028.13 2941.87,2157.97 3135,1964.85 3135,660 3164.13,630.87 3364.13,630.87 3425,570 3425,465 3441.19,448.81 v1(3464.99,448.81)
  Bottom Layer w30: v3(3723.98,780.67) 3783.75,720.91 v1(3783.75,710) ; v1(3843.75,710) 3843.75,730 3893.75,780
  other v1: 3758.71,295.75 3928.75,295.75 3423.75,304.37 3963.75,331.64 3478.75,335 3728.75,335 3533.75,345 3963.75,388.32 3720,390 3478.75,395 3533.75,410 3963.75,445 3728.75,448.36 3758.71,485 3928.75,485 3875,505 3815,510 3523.75,690 3583.75,710 3643.75,710 3703.75,710 3903.75,710 3968.75,710 3523.75,755 3523.75,815
  other v3: 3955,780 4015,780 4075,780 3603.98,780.67 3663.98,780.67 3955,845 4015,845 4075,845 3603.98,845.67 3663.98,845.67 3723.98,845.67 3955,905 4015,905 4075,905 3603.98,905.67 3663.98,905.67 3723.98,905.67
SYNC: R54.2 U9.41 U16.40 | length 1946.2
  Top Layer w10: v1(1985.28,3938.56) 1985.28,3960.76 1989.69,3965.16 U9.41@1989.69,3804.61 ; U16.40@3602.96,3812.4 3602.96,3899.21 v1(3613.75,3910)
  Signal Layer 2 w10: v1@1985.28,3939.07 v1(1985.28,3938.56) 2052.59,3938.56 2069.85,3955.82 3453.18,3955.82 3483.87,3925.13 3513.5,3925.13 3513.75,3924.88 3544.05,3924.87 3558.93,3910 v1(3613.75,3910)
SYNCIN: J1.11 U9.40 | length 3817.4
  Top Layer w10: U9.40@2009.37,3804.61 2009.37,3870.16 v1(2020.16,3880.94)
  Signal Layer 2 w10: J1.11@555,3110 495.43,3169.57 495.43,3250.43 457.62,3288.25 292.31,3288.25 235,3345.56 235,4324.17 280.83,4370 v1(2020,4370)
  Signal Layer 4 w10: v1(2020,4370) v1(2020.16,3880.94)
UVLO: C37.1 C68.1 D15.1 J1.20 U6.4 U9.10 U16.10 | length 9181.4
  Top Layer w10: v1(1723.94,3570.75) 1726.5,3573.31 U9.10@1797.76,3573.31 ; v1(3333.75,3570) 3344.85,3581.1 U16.10@3391.35,3581.1 ; U6.4@5072.13,3706.2 v13@5072.13,3775.61
  Top Layer w20: J1.20@855,3110 856.69,3111.69 D15.1@975,3111.69
  Signal Layer 2 w10: J1.20@855,3110 795.43,3169.57 795.43,3250.43 739.74,3306.12 301.75,3306.12 252.87,3355 252.87,4316.76 280.56,4344.44 v1@5068.19,4344.44
  Signal Layer 4 w10: v1(1705.28,4344.72) 1705.28,3650.44 1723.94,3631.79 v1(1723.94,3570.75) ; v1(3333.75,3570) 3338.62,3574.87 3338.75,4260 ; 3338.75,4070 v1(3338.75,4345) ; v13(5068.75,3779) v1(5068.75,4345)
V5: C1.1 C9.1 C17.1 C42.1 C44.1 C47.1 C55.1 C74.1 C76.1 C120.1 R13.1 R14.1 R15.1 R40.1 R42.1 R50.2 R51.2 R59.2 R66.1 R68.1 U1.8 U2.14 U4.8 U5.5 U10.4 U11.4 U12.4 U13.4 U17.4 U18.4 | length 20979.1
  Top Layer w10: v1@138.82,3746.18 R13.1@426.65,3746.18 ; C1.1@1283.39,3632.56 v1@1317.44,3632.56 ; C44.1@1480,277.56 1457.56,277.56 1445,265 1445,170 1540,75 3646.87,75 3693.75,121.87 C76.1@3693.75,162.44 ; C44.1@1488.03,285.59 U11.4@1534.72,285.59 ; U13.4@1527.56,2747.76 1527.56,2815 1530,2817.44 v1@1530,3030 ; C55.1@1534.42,2815.2 C55.1@1534.43,2815 ; U18.4@3635.05,161.97 C76.1@3693.28,161.97 ; U10.4@3976.07,2880.51 3977.13,2945.29 3977.93,2994.97 v1@3978.42,3025
  Top Layer w20: R59.2@192.44,2900 130,2962.44 130,4340 265,4475 v1(705,4475) v1(1320,4475) v6(1880,4475) v1(3473.75,4475) v1(3983.75,4475) 4823.75,4475 ; R13.1@426.65,3746.18 R15.1@576.65,3745.29 ; R15.1@576.65,3746.18 646.18,3746.18 667.09,3767.09 v1@667.09,3877.76 ; U2.14@635,3898.03 655.28,3877.76 ; v1(667.09,3880) v1@667.09,3877.76 ; C120.1@705,3877.76 v1@667.09,3877.76 ; U1.8@1224.68,3702.72 C1.1@1283.39,3644.02 ; R42.1@2486.85,4063.01 v1(2486.85,4104.25) ; R68.1@3983.75,4141.99 v1(3983.75,4195) ; C9.1@4316.62,3915.31 v1(4316.62,3952.76) ; C9.1@4324.65,3907.28 U4.8@4379.06,3907.28 ; R14.1@4823.75,4341.42 4823.75,4475 ; C17.1@4989.38,4105 4991.78,4102.6 U5.5@5069.93,4102.6 ; C17.1@4998.75,4105 5016.11,4122.36 5016.11,4438.89 4980,4475 4823.75,4475
  Signal Layer 2 w10: v1(2800,70) 2800.07,674.2 v1(2800.28,2564.72) v1(2800.28,3039.72)
  Signal Layer 4 w10: v1(1320,3630) v1(1320,4475) ; v1(1532.68,3040) 2530,3040 ; v1(1880.16,4115.94) v6@1880.16,4470 ; v1(2486.85,4104.25) v6(2486.85,4473.15) ; v1(2585,4472.74) 2585,3145 2530,3090 2530,3040 ; v1(3473.75,4195) v1(3473.75,4475) ; v1@3975,3040 2530,3040 ; v1(3983.75,4195) v1(3983.75,4475) ; v1(4316.62,3952.76) v1(4316.62,4477.87) v1@4318.75,4480
  Bottom Layer w10: v1(1880.16,4115.94) 1954.68,4115.94 1982.44,4088.19 R40.1@1982.44,4070 ; U17.4@2800.28,2460.87 v1(2800.28,2564.72) ; U12.4@2801.24,563.03 v1(2801.24,674.2)
  Bottom Layer w20: v1(1880.16,4115.94) 1881.09,4115.02 R51.2@1881.09,4068.2
  Bottom Layer w24: v1(3473.75,4195) R66.1@3474.24,4149.51
  other v1: 3980,3036.34 135,3750
V12_A: C94.1 C95.1 C96.1 C97.1 C98.1 C99.1 C100.1 C101.1 R2.2 R87.1 R92.2 R99.1 R102.2 V12_A.1 | length 8406.2
  Top Layer w10: v1(865,2207.13) 1030.87,2207.13 1053.15,2184.85 R87.1@1053.15,2128.9 ; v1(945,870) 950,865 1140,865 1148.15,873.15 R99.1@1148.15,946.06 ; R2.2@1230.94,3520 v1(1273.39,3520)
  Signal Layer 2 w10: v1(865,2207.13) 870.13,2212.25 870.13,2245.3 884.7,2259.87 894.6,2259.87 926.38,2291.66 926.38,2792.21 1462,3327.83 1462,3703 v1(1455,3710) ; v1(925,2051.42) 845,2131.42 845,2260 905,2320 905,2825 1273.39,3193.39 v1(1273.39,3520) ; v1(945,870) 945,2259.72 962.13,2276.85 962.13,2777.4 1547.13,3362.4 1547.13,3776 1590.8,3819.67 1718.2,3819.67 1720,3817.87 2436.87,3817.87 2454.87,3799.87 2454.87,3759.7 2430,3734.82 v1@2430,3730
  Bottom Layer w10: v1(1455,3710) 1572.02,3710.94 R102.2@1572.6,3710.94 ; R92.2@2332.72,3714.65 2348.07,3730 v1(2425,3730) v1@2430,3730
  other v1: 650,360 710,360 775,360 650,410 710,410 775,410 650,805 715,805 775,805 650,855 715,855 775,855 910,920 910,965 910,1025 1000,1025 1061,1025 1122,1025 1183,1025 1244,1025 910,1070 1000,1070 1061,1070 1122,1070 1185,1070 1244,1070 1150,1330 1150,1570 1150,1820 1250,1991.42 922.5,1992.13 990,1992.13 1040,1992.13 1095,1992.13 1207.5,1992.13 992.5,2051.42 1042.5,2051.42 1097.5,2051.42 1207.5,2051.42 1250,2050.71 1250,2110 1207.5,2110.71 1207.5,2170
  other v2: 129.96,1020 169.96,1020 209.96,1020 249.96,1020 736.23,1020 776.23,1020 816.23,1020 129.96,1060 169.96,1060 209.96,1060 249.96,1060 816.23,1060 129.96,1100 169.96,1100 209.96,1100 249.96,1100 816.23,1100 129.96,1140 169.96,1140 209.96,1140 249.96,1140 129.96,1180 169.96,1180 209.96,1180 249.96,1180 129.96,1220 169.96,1220 209.96,1220 249.96,1220 129.96,1270 169.96,1270 209.96,1270 249.96,1270 129.96,1310 169.96,1310 209.96,1310 249.96,1310 129.96,1350 169.96,1350 209.96,1350 249.96,1350 129.96,1390 169.96,1390 209.96,1390 249.96,1390 816.23,1390 129.96,1430 169.96,1430 209.96,1430 249.96,1430 816.23,1430 129.96,1470 169.96,1470 209.96,1470 249.96,1470 736.23,1470 776.23,1470 816.23,1470
V12_B: C112.1 C114.1 C115.1 C116.1 C117.1 C118.1 C119.1 C127.1 R16.1 R111.2 R117.2 R123.2 R127.2 V12_B.1 | length 8034.7
  Top Layer w6: V12_B.1@5013.78,1270 V12_B.1@5218.75,1270
  Top Layer w10: v1(4274.06,3440.31) R16.1@4316.5,3440.31 ; v1(4443.75,2390) 4448.75,2395 4585.87,2395 4599.97,2380.91 R111.2@4599.97,2313.42 ; R123.2@4599.59,1025.1 4599.59,954.15 4608.75,945 4761.62,945 v1(4771.62,955)
  Signal Layer 2 w10: v1(3083.75,3730) 3086.55,3732.8 3171.37,3732.8 3253.44,3814.87 3778.62,3814.87 3803.69,3839.94 4038.81,3839.94 4053.75,3825 4053.75,3570 4503.75,3120 4503.75,1222.87 v1(4771.62,955) ; v1(4028.75,3761.81) 4028.75,3565.28 4488.75,3105.28 4488.75,2435 v1(4443.75,2390) ; v1(4274.06,3440.31) 4274.06,3400.24 4539.5,3134.81 4539.5,2244.25 v1(4553.75,2230) ; V12_B.1@4908.75,1500 V12_B.1@4908.75,1515
  Bottom Layer w10: v1@3086.55,3732.8 R127.2@3176.23,3732.8 ; R117.2@3936.86,3732.8 3999.73,3732.8 v1(4028.75,3761.81)
  other v1: 4947.08,425 4998.75,425 5050.41,425 4947.08,475 4998.75,475 5050.41,475 4950.41,875 5002.08,875 5053.75,875 4950.41,925 5002.08,925 5053.75,925 4443.75,970 4443.75,1015 4443.75,1065 4443.75,1115 4493.75,1115 4538.75,1115 4693.75,1115 4743.75,1115 4443.75,1155 4493.75,1155 4538.75,1155 4658.75,1155 4728.75,1155 4468.75,1420 4463.75,1665 4463.75,1905 4473.75,2170 4553.75,2170 4623.75,2170 4683.75,2170 4743.75,2170 4473.75,2230 4623.75,2230 4683.75,2230 4743.75,2230 4758.75,2265 4758.75,2315 4758.75,2365
  other v2: 4838.77,1085 4878.77,1085 4918.77,1085 5405.04,1085 5445.04,1085 5485.04,1085 5525.04,1085 4838.77,1125 5405.04,1125 5445.04,1125 5485.04,1125 5525.04,1125 4838.77,1165 5405.04,1165 5445.04,1165 5485.04,1165 5525.04,1165 5405.04,1205 5445.04,1205 5485.04,1205 5525.04,1205 5405.04,1245 5445.04,1245 5485.04,1245 5525.04,1245 5405.04,1285 5445.04,1285 5485.04,1285 5525.04,1285 5405.04,1335 5445.04,1335 5485.04,1335 5525.04,1335 5405.04,1375 5445.04,1375 5485.04,1375 5525.04,1375 5405.04,1415 5445.04,1415 5485.04,1415 5525.04,1415 4838.77,1455 5405.04,1455 5445.04,1455 5485.04,1455 5525.04,1455 4838.77,1495 5405.04,1495 5445.04,1495 5485.04,1495 5525.04,1495 4838.77,1535 4878.77,1535 4918.77,1535 5405.04,1535 5445.04,1535 5485.04,1535 5525.04,1535
VCC1: C16.1 C22.1 C23.1 C45.1 C75.1 D7.2 D8.1 D12.2 D13.2 D18.2 D19.2 R38.2 R56.2 R81.2 U5.1 U6.10 U9.19 U16.19 | length 12135.1
  Top Layer w10: C45.1@1970,3314.61 U9.19@1970,3479.8 ; C75.1@3553.87,3330.12 3563.59,3339.84 U16.19@3563.59,3487.6 ; v1(4888.75,3760) 4918.59,3730.16 U6.10@4918.59,3706.2 ; v1@4966.31,3997.56 R38.2@4966.31,3955 5468.75,3955 ; D7.2@5243.75,3564.47 5463.22,3564.47
  Top Layer w20: C45.1@1950,3294.61 1951.78,3294.61 1999.37,3247.01 1999.37,3245.23 2008.66,3235.94 2008.66,3164.8 2019.13,3154.33 2629.33,3154.33 v1(2630,3155) 3456.39,3155 3490.24,3188.86 3490.24,3268.27 3541.97,3320 C75.1@3543.75,3320 ; U5.1@5178.2,4102.6 5466.15,4102.6
  Top Layer w24: v1(2385,4515) v1(2630,4515) v1(3958.75,4515) 5198.75,4515 5468.75,4245 5468.75,3955 5468.75,2715 5423.75,2670 C22.1@5354.06,2670
  Top Layer w26: R56.2@2342.49,3645 2351.54,3635.94 v1@2385.16,3635.94
  Top Layer w30: D13.2@1855,3304.72 D12.2@2048.82,3304.72 ; D19.2@3448.75,3330.12 3553.87,3330.12 D18.2@3638.75,3330.12
  Top Layer w40: C22.1@5354.06,2670 D8.1@5354.06,2800.94
  Signal Layer 4 w10: v1(2385,3635) v1@2385.03,4505.03 ; v1(3958.75,4515) 3958.87,4514.87 3958.87,4174.7 3978.75,4154.82 v1(3978.75,3635) ; v1(4888.75,3760) 4888.75,3985 4903.75,4000 v1(4968.75,4000)
  Signal Layer 4 w20: v1(2630,3155) v1@2630,4505
  Bottom Layer w20: R81.2@3933.28,3640 v1@3973.75,3640
  other v1: 5343.75,2640 5388.75,2640 5323.75,2865 5378.75,2865
VCCA1: C46.1 R56.1 U9.29 U9.31 | length 365
  Top Layer w10: U9.29@2122.56,3612.68 2174.26,3612.68 2191.94,3595 v1(2205,3595) ; U9.31@2122.56,3652.05 R56.1@2276.38,3652.05
  Bottom Layer w10: v1(2205,3595) 2205,3624.74 v1(2225.15,3644.89) 2268.66,3644.89 C46.1@2282.6,3630.94
VCCA2: C77.1 R81.1 U16.29 U16.31 | length 380.1
  Top Layer w10: U16.29@3716.15,3620.47 3793.28,3620.47 v1(3808.75,3605) ; U16.31@3716.15,3659.84 3788.59,3659.84 3798.75,3670 C77.1@3876.19,3670 ; v1@3859.03,3659.84 C77.1@3863.75,3655.13
  Bottom Layer w10: v1(3808.75,3605) 3803.87,3609.87 3803.87,3645.3 3818.44,3659.87 v1(3859,3659.87) R81.1@3863.75,3655.13
VCCX_bais: C28.1 D7.1 R32.1 U6.16 | length 1642.5
  Top Layer w10: C28.1@4988.75,3341.39 5046.54,3399.19 U6.16@5046.54,3481.8
  Top Layer w20: C28.1@4988.75,3341.39 v1(4988.75,3370) ; v1(5243.75,3370) D7.1@5243.75,3435.53
  Signal Layer 2 w10: v1(4988.75,3370) v1(5243.75,3370) 5333.75,3370 5373.75,3410 5373.75,3925 5303.75,3995 v1(5023.75,3995)
  Bottom Layer w10: R32.1@5023.75,3906.56 v1(5023.75,3995)
VINX1: R39.1 R45.1 U9.4 | length 1010.9
  Top Layer w10: v1(1640.16,3670.94) 1648.98,3679.76 R45.1@1690.16,3679.76 1701.81,3691.42 U9.4@1797.76,3691.42 ; R39.1@2335.79,3522.2 R39.1@2336.34,3522.76
  Signal Layer 2 w10: v1(1640.16,3670.94) 1640.16,3594.84 1735,3500 2339.21,3500 v1(2360.16,3520.94)
VINX2: R65.1 R71.1 U16.4 | length 1014.9
  Top Layer w10: v1@3226.19,3687.56 R71.1@3273.75,3687.56 ; R71.1@3285.4,3699.21 U16.4@3391.35,3699.21 ; v1@3931.31,3521.81 R65.1@3931.31,3540
  Signal Layer 2 w10: v1(3223.75,3690) 3223.75,3576.57 3282.98,3521.32 v1(3931.8,3521.32)
Vmid: C18.1 C19.1 C20.1 C38.1 C69.1 C102.1 C103.1 C104.1 C105.1 C106.1 C107.1 C108.1 C109.1 C121.1 C122.1 C123.1 C126.1 D22.1 D24.1 D26.1 D28.1 Q7.3 Q10.5 Q10.6 Q10.7 Q10.8 Q10.9 Q13.5 Q13.6 Q13.7 Q13.8 Q13.9 Q14.5 Q14.6 Q14.7 Q14.8 Q14.9 Q17.5 Q17.6 Q17.7 Q17.8 Q17.9 Q18.5 Q18.6 Q18.7 Q18.8 Q18.9 Q21.5 Q21.6 Q21.7 Q21.8 Q21.9 Q22.5 Q22.6 Q22.7 Q22.8 Q22.9 Q25.5 Q25.6 Q25.7 Q25.8 Q25.9 R1.1 R17.2 R30.2 R63.1 U6.1 U9.6 U16.6 | length 9324.3
  Top Layer w10: 1021.5,3046.5 R63.1@1021.5,3010 1090.85,3079.35 v1(1355,3079.35) ; 1255,3080 v1@1354.35,3080 ; v1(1730.16,3660.75) 1738.86,3652.05 U9.6@1797.76,3652.05 ; v1@3313.91,3659.84 U16.6@3391.35,3659.84 ; R17.2@4439.36,4207.58 v1@4531.17,4207.58 ; U6.1@5148.91,3706.2 5148.91,3756.6 R30.2@5196.31,3804
  Top Layer w20: v1(4613.75,2895) C18.1@4650.68,2895 ; U6.1@5148.91,3714 C20.1@5228.75,3714 ; C20.1@5228.91,3713.83 v1(5283.75,3713.83)
  Top Layer w24: R1.1@1295.94,4110 v1(1355,4110)
  Top Layer w30: C18.1@4650.44,2880 4650.68,2880 Q7.3@4691.11,2880
  Top Layer w40: v1@1354.35,3080 v9(1760,3080) 2900,3080 ; 2905,2735 2900,2740 2900,3080 ; C19.1@4650.68,2805 4650.68,2880 C18.1@4650.68,2895 4650.68,2923.07 4493.75,3080 v9(3300,3080) 2900,3080
  Signal Layer 2 w20: v1@4729.91,3713.83 v1(5283.75,3713.83)
  Signal Layer 4 w10: v1(1355,3079.35) v1(1355,4110) ; v1(4533.75,4205) 4533.75,3770 4588.75,3715 v1(4733.75,3715)
  Signal Layer 4 w20: v1(4613.75,2895) 4613.75,3415 4733.75,3535 v1(4733.75,3715)
  Signal Layer 4 w24: v1(1730.16,3660.75) 1760,3630.91 v9(1760,3080) ; v9(3300,3080) 3203.75,3176.25 3203.75,3550 v1(3313.75,3660)
  other v1: 3220,1060 3255,1060 2325,1110 2360,1110 3220,1190 3255,1190 2325,1240 2360,1240 3220,1311.19 3255,1311.19 2325,1361.19 2360,1361.19 3220,1457.83 3255,1457.83 2325,1507.83 2360,1507.83 3215,1615 3250,1615 2325,1619.02 2360,1619.02 3220,1780 3255,1780 2325,1830 2360,1830 3220,1925 3255,1925 2320,2019.28 2355,2019.28
  other v3: 2295,340 2355,340 2415,340 3218.75,360 3278.75,360 3338.75,360 2295,405 2355,405 2415,405 3218.75,425 3278.75,425 3338.75,425 2295,465 2355,465 2415,465 3218.75,485 3278.75,485 3338.75,485 2295,700 2355,700 2415,700 3223.91,709.65 3283.91,709.65 3343.91,709.65 2295,765 2355,765 2415,765 3223.91,774.65 3283.91,774.65 3343.91,774.65 2295,825 2355,825 2415,825 3223.91,834.65 3283.91,834.65 3343.91,834.65 2280,2220 2340,2220 2400,2220 3154.5,2222.91 3214.5,2222.91 3274.5,2222.91 2280,2285 2340,2285 2400,2285 3154.5,2287.91 3214.5,2287.91 3274.5,2287.91 2280,2345 2340,2345 2400,2345 3154.5,2347.91 3214.5,2347.91 3274.5,2347.91 2280,2575 2340,2575 2400,2575 3180,2575 3240,2575 3300,2575 2280,2640 2340,2640 2400,2640 3180,2640 3240,2640 3300,2640 2280,2700 2340,2700 2400,2700 3180,2700 3240,2700 3300,2700
pads on no net: J1.14 J1.17 U3.3 U5.3 U5.4 U6.11 U9.3 U9.5 U9.7 U9.16 U9.21 U9.32 U10.5 U10.6 U11.5 U11.6 U12.5 U12.6 U13.5 U13.6 U16.3 U16.5 U16.7 U16.16 U16.21 U16.32 U17.5 U17.6 U18.5 U18.6

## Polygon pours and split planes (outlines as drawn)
PGND on Bottom Layer "BOTTOM_LAYER_PGND_P1049" (solid, remove dead copper, pour order 1049): 5643.75,0 5643.75,3703.99 5624.76,3685 0,3685 0,5 5638.75,5
AGND on Bottom Layer "Signal Layer 6-AGND6" (solid, remove dead copper, pour order 1048): 3364,3534 3706,3534 4090,3150 4495,3150 4940,3665 5643.75,3665 5643.75,4585 0,4585 0,2860 1120,2860 1790,3530 2095,3530 2430,3195 3025,3195
Vmid on Bottom Layer "Top Layer-Vmid4" (solid, remove dead copper, pour order 1047): 3325,911.7 3385,851.7 3385,220 3360,195 2410,195 2235,370 2235,2848.39 2251.61,2865 3200,2865 3325,2740
NetC21_1 on Bottom Layer "BOTTOM_LAYER_NETC21_1_P1038" (solid, remove dead copper, pour order 1038): 4700,3095 4710,3105 4910,3105 4945,3070 4945,2930 4900,2885 4770,2885 4700,2955
NetD8_2 on Bottom Layer "Top Layer-NetD8_2" (solid, remove dead copper, pour order 1035): 5180,3065 5375,3065 5395,3045 5395,2925 5385,2915 5180,2915 5170,2925 5170,3055
V12_B on Bottom Layer "BOTTOM_LAYER_V12_B_P1031" (solid, remove dead copper, pour order 1031): 5075,760 5090,775 5090,920 5063.44,946.56 4936.56,946.56 4915,925 4915,775 4930,760
V12_A on Bottom Layer "BOTTOM_LAYER_V12_A_P1033" (solid, remove dead copper, pour order 1033): 785,245 800,260 800,405 773.44,431.56 646.56,431.56 625,410 625,260 640,245
V12_A on Bottom Layer "BOTTOM_LAYER_V12_A_P1032" (solid, remove dead copper, pour order 1032): 785,695 800,710 800,855 773.44,881.56 646.56,881.56 625,860 625,710 640,695
V12_B on Bottom Layer "BOTTOM_LAYER_V12_B_P1030" (solid, remove dead copper, pour order 1030): 5075,305 5090,320 5090,465 5063.44,491.56 4936.56,491.56 4915,470 4915,320 4930,305
AGND on Bottom Layer "BOTTOM_LAYER_AGND_P022" (solid, remove dead copper, pour order 1037): 2669.44,683.41 2696.03,710 2829.59,710 2849.44,690.15 2849.44,508.41 2824.44,483.41 2689.44,483.41 2669.44,503.41
VCC1 on Bottom Layer "BOTTOM_LAYER_VCC1_P000" (solid, remove dead copper, pour order 1034): 5388.51,2617.57 5407.25,2638.81 5407.25,2881.67 5389.67,2900 5312.56,2900 5289.51,2876.95 5289.51,2657.12 5325.33,2617.57
NetL8_1 on Bottom Layer "BOTTOM_LAYER_NETL8_1_P1042" (solid, remove dead copper, pour order 1042): 994.25,2395.75 1205,2185 1410,2185 1510,2285 1510,2740.51 1420.51,2830 1017.6,2830 994.25,2809.57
